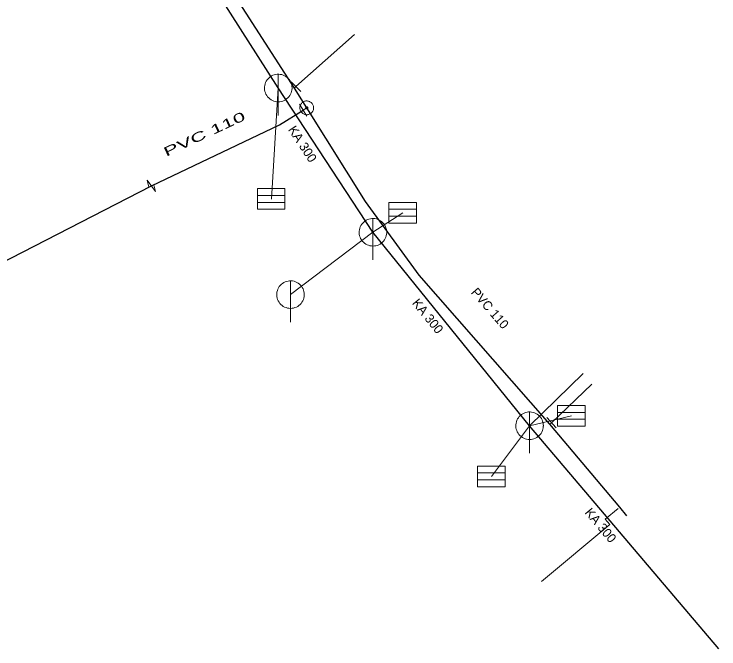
# Model space of a CAD drawing. Extents: x -688296 to -687852, y -973332 to -972816.
# Drawn here: x -687935.8 to -687884.6, y -973158.8 to -973112.8 of the extents above; entities that cross this region are included whole.
import ezdxf
from ezdxf.enums import TextEntityAlignment as Align

# ---------------------------------------------------------------- set-up
doc = ezdxf.new("R2010")
doc.units = 0
doc.header["$LTSCALE"] = 0.27
for name, color, linetype, lineweight in [('1', 7, 'Continuous', 25), ('11', 7, 'Continuous', 13), ('13', 7, 'Continuous', 13), ('14', 7, 'Continuous', 13), ('17', 7, 'Continuous', 25), ('22', 7, 'Continuous', 13), ('34', 7, 'Continuous', 13), ('47', 7, 'Continuous', 13)]:
    doc.layers.add(name, color=color, linetype=linetype, lineweight=lineweight)

msp = doc.modelspace()

# ---------------------------------------------------------------- linework, layer by layer
at = {"layer": '11'}
for p, q in [((-687917.11, -973126.22), (-687916.61, -973118.16)), ((-687907.57, -973127.219), (-687909.739, -973128.629)), ((-687915.719, -973133.149), (-687909.739, -973128.629)), ((-687894.48, -973138.87), (-687898.37, -973142.66)), ((-687895.32, -973141.949), (-687898.37, -973142.66)), ((-687901.129, -973146.34), (-687898.37, -973142.66))]:
    msp.add_line(p, q, dxfattribs=at)
at = {"layer": '13'}
for p, q in [((-687915.323, -973118.063), (-687911.079, -973114.27)), ((-687896.776, -973142.45), (-687893.84, -973139.64))]:
    msp.add_line(p, q, dxfattribs=at)
msp.add_lwpolyline([(-687891.943, -973148.654), (-687892.879, -973149.43), (-687892.55, -973149.82), (-687897.51, -973153.949)], dxfattribs=at)
at = {"layer": '14', "lineweight": 25}
for p, q in [((-687916.609, -973118.16), (-687924.829, -973105.26)), ((-687909.739, -973128.629), (-687916.609, -973118.16)), ((-687898.37, -973142.66), (-687909.739, -973128.629)), ((-687884.629, -973158.85), (-687898.37, -973142.66))]:
    msp.add_line(p, q, dxfattribs=at)
at = {"layer": '14'}
for p, q in [((-687915.43, -973118.17), (-687915.323, -973118.063)), ((-687914.539, -973119.599), (-687914.809, -973119.77)), ((-687896.89, -973142.55), (-687896.776, -973142.45))]:
    msp.add_line(p, q, dxfattribs=at)
at = {"layer": '17'}
for points in [[(-687914.539, -973119.599), (-687915.43, -973118.17), (-687922.94, -973106.52), (-687923.129, -973106.219)], [(-687891.309, -973149.189), (-687891.82, -973148.57), (-687896.89, -973142.55), (-687906.39, -973131.739), (-687910.28, -973126.39), (-687914.539, -973119.599)], [(-687925.819, -973125.269), (-687916.51, -973120.829), (-687914.809, -973119.77)], [(-687972.436, -973150.573), (-687949.647, -973137.493), (-687925.819, -973125.269)]]:
    msp.add_lwpolyline(points, dxfattribs=at)
at = {"layer": '22'}
for p, q in [((-687916.609, -973120.16), (-687916.608, -973117.16)), ((-687918.12, -973125.962), (-687916.12, -973125.962)), ((-687918.12, -973126.462), (-687916.12, -973126.462)), ((-687908.581, -973126.962), (-687906.581, -973126.962)), ((-687909.739, -973130.629), (-687909.738, -973127.629)), ((-687908.581, -973127.462), (-687906.581, -973127.462)), ((-687915.719, -973135.149), (-687915.718, -973132.149)), ((-687898.37, -973144.66), (-687898.369, -973141.66)), ((-687896.331, -973141.692), (-687894.331, -973141.692)), ((-687896.331, -973142.192), (-687894.331, -973142.192)), ((-687902.14, -973146.083), (-687900.14, -973146.083)), ((-687902.14, -973146.583), (-687900.14, -973146.583))]:
    msp.add_line(p, q, dxfattribs=at)
for points in [[(-687915.609, -973118.16), (-687915.614, -973118.051), (-687915.632, -973117.943), (-687915.662, -973117.837), (-687915.702, -973117.736), (-687915.754, -973117.639), (-687915.816, -973117.549), (-687915.888, -973117.466), (-687915.968, -973117.392), (-687916.056, -973117.326), (-687916.15, -973117.271), (-687916.25, -973117.226), (-687916.355, -973117.193), (-687916.462, -973117.171), (-687916.571, -973117.161), (-687916.681, -973117.163), (-687916.789, -973117.177), (-687916.896, -973117.202), (-687916.999, -973117.239), (-687917.097, -973117.288), (-687917.189, -973117.346), (-687917.275, -973117.415), (-687917.352, -973117.492), (-687917.421, -973117.578), (-687917.48, -973117.67), (-687917.528, -973117.768), (-687917.565, -973117.871), (-687917.591, -973117.978), (-687917.605, -973118.086), (-687917.608, -973118.196), (-687917.598, -973118.305), (-687917.577, -973118.412), (-687917.543, -973118.516), (-687917.499, -973118.616), (-687917.444, -973118.711), (-687917.378, -973118.799), (-687917.304, -973118.879), (-687917.221, -973118.951), (-687917.131, -973119.013), (-687917.035, -973119.065), (-687916.933, -973119.106), (-687916.828, -973119.136), (-687916.72, -973119.154), (-687916.61, -973119.16), (-687916.501, -973119.154), (-687916.393, -973119.136), (-687916.288, -973119.107), (-687916.186, -973119.066), (-687916.089, -973119.014), (-687915.999, -973118.952), (-687915.916, -973118.881), (-687915.841, -973118.801), (-687915.776, -973118.713), (-687915.72, -973118.619), (-687915.676, -973118.519), (-687915.642, -973118.415), (-687915.62, -973118.307), (-687915.61, -973118.198)], [(-687918.12, -973125.462), (-687916.12, -973125.462), (-687916.12, -973126.962), (-687918.12, -973126.962)], [(-687908.581, -973126.462), (-687906.581, -973126.462), (-687906.581, -973127.962), (-687908.581, -973127.962)], [(-687908.739, -973128.629), (-687908.744, -973128.52), (-687908.762, -973128.412), (-687908.792, -973128.306), (-687908.832, -973128.205), (-687908.884, -973128.108), (-687908.946, -973128.018), (-687909.018, -973127.935), (-687909.098, -973127.861), (-687909.186, -973127.795), (-687909.28, -973127.74), (-687909.38, -973127.695), (-687909.485, -973127.662), (-687909.592, -973127.64), (-687909.701, -973127.63), (-687909.811, -973127.632), (-687909.919, -973127.646), (-687910.026, -973127.671), (-687910.129, -973127.708), (-687910.227, -973127.757), (-687910.319, -973127.815), (-687910.405, -973127.884), (-687910.482, -973127.961), (-687910.551, -973128.047), (-687910.61, -973128.139), (-687910.658, -973128.237), (-687910.695, -973128.34), (-687910.721, -973128.447), (-687910.735, -973128.555), (-687910.738, -973128.665), (-687910.728, -973128.774), (-687910.707, -973128.881), (-687910.673, -973128.985), (-687910.629, -973129.085), (-687910.574, -973129.18), (-687910.508, -973129.268), (-687910.434, -973129.348), (-687910.351, -973129.42), (-687910.261, -973129.482), (-687910.165, -973129.534), (-687910.063, -973129.575), (-687909.958, -973129.605), (-687909.85, -973129.623), (-687909.74, -973129.629), (-687909.631, -973129.623), (-687909.523, -973129.605), (-687909.418, -973129.576), (-687909.316, -973129.535), (-687909.219, -973129.483), (-687909.129, -973129.421), (-687909.046, -973129.35), (-687908.971, -973129.27), (-687908.906, -973129.182), (-687908.85, -973129.088), (-687908.806, -973128.988), (-687908.772, -973128.884), (-687908.75, -973128.776), (-687908.74, -973128.667)], [(-687914.719, -973133.149), (-687914.724, -973133.04), (-687914.742, -973132.932), (-687914.772, -973132.826), (-687914.812, -973132.725), (-687914.864, -973132.628), (-687914.926, -973132.538), (-687914.998, -973132.455), (-687915.078, -973132.381), (-687915.166, -973132.315), (-687915.26, -973132.26), (-687915.36, -973132.215), (-687915.465, -973132.182), (-687915.572, -973132.16), (-687915.681, -973132.15), (-687915.791, -973132.152), (-687915.899, -973132.166), (-687916.006, -973132.191), (-687916.109, -973132.228), (-687916.207, -973132.277), (-687916.299, -973132.335), (-687916.385, -973132.404), (-687916.462, -973132.481), (-687916.531, -973132.567), (-687916.59, -973132.659), (-687916.638, -973132.757), (-687916.675, -973132.86), (-687916.701, -973132.967), (-687916.715, -973133.075), (-687916.718, -973133.185), (-687916.708, -973133.294), (-687916.687, -973133.401), (-687916.653, -973133.505), (-687916.609, -973133.605), (-687916.554, -973133.7), (-687916.488, -973133.788), (-687916.414, -973133.868), (-687916.331, -973133.94), (-687916.241, -973134.002), (-687916.145, -973134.054), (-687916.043, -973134.095), (-687915.938, -973134.125), (-687915.83, -973134.143), (-687915.72, -973134.149), (-687915.611, -973134.143), (-687915.503, -973134.125), (-687915.398, -973134.096), (-687915.296, -973134.055), (-687915.199, -973134.003), (-687915.109, -973133.941), (-687915.026, -973133.87), (-687914.951, -973133.79), (-687914.886, -973133.702), (-687914.83, -973133.608), (-687914.786, -973133.508), (-687914.752, -973133.404), (-687914.73, -973133.296), (-687914.72, -973133.187)], [(-687896.331, -973141.192), (-687894.331, -973141.192), (-687894.331, -973142.692), (-687896.331, -973142.692)], [(-687897.37, -973142.66), (-687897.375, -973142.551), (-687897.393, -973142.443), (-687897.423, -973142.337), (-687897.463, -973142.236), (-687897.515, -973142.139), (-687897.577, -973142.049), (-687897.649, -973141.966), (-687897.729, -973141.892), (-687897.817, -973141.826), (-687897.911, -973141.771), (-687898.011, -973141.726), (-687898.116, -973141.693), (-687898.223, -973141.671), (-687898.332, -973141.661), (-687898.442, -973141.663), (-687898.55, -973141.677), (-687898.657, -973141.702), (-687898.76, -973141.739), (-687898.858, -973141.788), (-687898.95, -973141.846), (-687899.036, -973141.915), (-687899.113, -973141.992), (-687899.182, -973142.078), (-687899.241, -973142.17), (-687899.289, -973142.268), (-687899.326, -973142.371), (-687899.352, -973142.478), (-687899.366, -973142.586), (-687899.369, -973142.696), (-687899.359, -973142.805), (-687899.338, -973142.912), (-687899.304, -973143.016), (-687899.26, -973143.116), (-687899.205, -973143.211), (-687899.139, -973143.299), (-687899.065, -973143.379), (-687898.982, -973143.451), (-687898.892, -973143.513), (-687898.796, -973143.565), (-687898.694, -973143.606), (-687898.589, -973143.636), (-687898.481, -973143.654), (-687898.371, -973143.66), (-687898.262, -973143.654), (-687898.154, -973143.636), (-687898.049, -973143.607), (-687897.947, -973143.566), (-687897.85, -973143.514), (-687897.76, -973143.452), (-687897.677, -973143.381), (-687897.602, -973143.301), (-687897.537, -973143.213), (-687897.481, -973143.119), (-687897.437, -973143.019), (-687897.403, -973142.915), (-687897.381, -973142.807), (-687897.371, -973142.698)], [(-687902.14, -973145.583), (-687900.14, -973145.583), (-687900.14, -973147.083), (-687902.14, -973147.083)]]:
    msp.add_lwpolyline(points, close=True, dxfattribs=at)
at = {"layer": '34'}
for p, q in [((-687915.677, -973117.71), (-687914.969, -973118.416)), ((-687915.073, -973119.345), (-687914.544, -973120.194)), ((-687897.106, -973142.074), (-687896.446, -973142.825))]:
    msp.add_line(p, q, dxfattribs=at)
at = {"layer": '47'}
msp.add_line((-687926.122, -973124.859), (-687926, -973125.355), dxfattribs=at)
for points in [[(-687914.273, -973120.022), (-687914.23, -973119.992), (-687914.191, -973119.957), (-687914.156, -973119.919), (-687914.124, -973119.878), (-687914.097, -973119.832), (-687914.075, -973119.784), (-687914.058, -973119.735), (-687914.047, -973119.684), (-687914.04, -973119.633), (-687914.039, -973119.58), (-687914.043, -973119.528), (-687914.054, -973119.477), (-687914.069, -973119.427), (-687914.09, -973119.378), (-687914.115, -973119.333), (-687914.145, -973119.29), (-687914.18, -973119.251), (-687914.219, -973119.215), (-687914.259, -973119.184), (-687914.305, -973119.157), (-687914.353, -973119.135), (-687914.402, -973119.118), (-687914.453, -973119.106), (-687914.505, -973119.099), (-687914.557, -973119.099), (-687914.609, -973119.103), (-687914.661, -973119.113), (-687914.71, -973119.129), (-687914.759, -973119.15), (-687914.804, -973119.175), (-687914.847, -973119.205), (-687914.886, -973119.24), (-687914.923, -973119.278), (-687914.953, -973119.319), (-687914.98, -973119.365), (-687915.003, -973119.412), (-687915.02, -973119.461), (-687915.032, -973119.512), (-687915.038, -973119.565), (-687915.038, -973119.617), (-687915.034, -973119.669), (-687915.024, -973119.72), (-687915.008, -973119.77), (-687914.987, -973119.819), (-687914.962, -973119.864), (-687914.932, -973119.907), (-687914.897, -973119.946), (-687914.86, -973119.982), (-687914.818, -973120.013), (-687914.772, -973120.04), (-687914.725, -973120.063), (-687914.676, -973120.079), (-687914.625, -973120.091), (-687914.573, -973120.097), (-687914.52, -973120.098), (-687914.468, -973120.094), (-687914.417, -973120.083), (-687914.367, -973120.068), (-687914.318, -973120.047)], [(-687914.495, -973119.668), (-687914.487, -973119.663), (-687914.482, -973119.657), (-687914.476, -973119.651), (-687914.471, -973119.644), (-687914.466, -973119.637), (-687914.463, -973119.629), (-687914.459, -973119.621), (-687914.458, -973119.613), (-687914.457, -973119.604), (-687914.457, -973119.595), (-687914.457, -973119.587), (-687914.459, -973119.578), (-687914.462, -973119.57), (-687914.464, -973119.563), (-687914.469, -973119.555), (-687914.474, -973119.547), (-687914.48, -973119.542), (-687914.486, -973119.536), (-687914.493, -973119.531), (-687914.5, -973119.526), (-687914.508, -973119.523), (-687914.516, -973119.519), (-687914.524, -973119.518), (-687914.533, -973119.516), (-687914.542, -973119.517), (-687914.55, -973119.517), (-687914.559, -973119.519), (-687914.567, -973119.522), (-687914.574, -973119.524), (-687914.582, -973119.529), (-687914.59, -973119.534), (-687914.595, -973119.54), (-687914.601, -973119.546), (-687914.606, -973119.553), (-687914.611, -973119.56), (-687914.615, -973119.567), (-687914.618, -973119.576), (-687914.619, -973119.584), (-687914.621, -973119.593), (-687914.62, -973119.602), (-687914.62, -973119.61), (-687914.618, -973119.619), (-687914.615, -973119.627), (-687914.613, -973119.634), (-687914.608, -973119.642), (-687914.603, -973119.65), (-687914.597, -973119.655), (-687914.591, -973119.661), (-687914.584, -973119.666), (-687914.577, -973119.671), (-687914.57, -973119.675), (-687914.561, -973119.678), (-687914.553, -973119.679), (-687914.544, -973119.68), (-687914.535, -973119.68), (-687914.527, -973119.68), (-687914.518, -973119.678), (-687914.51, -973119.675), (-687914.503, -973119.673)]]:
    msp.add_lwpolyline(points, close=True, dxfattribs=at)
msp.add_lwpolyline([(-687926.122, -973124.859), (-687925.515, -973125.678), (-687925.637, -973125.182)], dxfattribs=at)

# ---------------------------------------------------------------- texts
at = {"layer": '1', "width": 1.8}
msp.add_text('PVC 110 ', height=0.6667, rotation=25, dxfattribs=at).set_placement((-687921.6289, -973121.7029), align=Align.CENTER)
msp.add_text('PVC 110 ', height=0.6667, rotation=25, dxfattribs=at).set_placement((-687921.6289, -973121.7029), align=Align.CENTER)
msp.add_text('PVC 110 ', height=0.6667, rotation=25, dxfattribs=at).set_placement((-687921.6289, -973121.7029), align=Align.CENTER)
msp.add_text('PVC 110 ', height=0.6667, rotation=25, dxfattribs=at).set_placement((-687921.6289, -973121.7029), align=Align.CENTER)
msp.add_text('PVC 110 ', height=0.6667, rotation=25, dxfattribs=at).set_placement((-687921.6289, -973121.7029), align=Align.CENTER)
at = {"layer": '1'}
for s, rotation, p in [('KA 300', 303, (-687915.1226, -973122.4028)), ('KA 300', 303, (-687915.1226, -973122.4028)), ('KA 300', 303, (-687915.1226, -973122.4028)), ('KA 300', 303, (-687915.1226, -973122.4028)), ('KA 300', 303, (-687915.1226, -973122.4028)), ('PVC 110 ', 311, (-687901.4092, -973134.4542)), ('PVC 110 ', 311, (-687901.4092, -973134.4542)), ('PVC 110 ', 311, (-687901.4092, -973134.4542)), ('PVC 110 ', 311, (-687901.4092, -973134.4542)), ('PVC 110 ', 311, (-687901.4092, -973134.4542)), ('KA 300', 309, (-687906.0127, -973134.9188)), ('KA 300', 309, (-687906.0127, -973134.9188)), ('KA 300', 309, (-687906.0127, -973134.9188)), ('KA 300', 309, (-687906.0127, -973134.9188)), ('KA 300', 309, (-687906.0127, -973134.9188)), ('KA 300', 310, (-687893.4649, -973150.0985)), ('KA 300', 310, (-687893.4649, -973150.0985)), ('KA 300', 310, (-687893.4649, -973150.0985)), ('KA 300', 310, (-687893.4649, -973150.0985)), ('KA 300', 310, (-687893.4649, -973150.0985))]:
    msp.add_text(s, height=0.6667, rotation=rotation, dxfattribs=at).set_placement(p, align=Align.CENTER)

doc.saveas('drawing.dxf')
